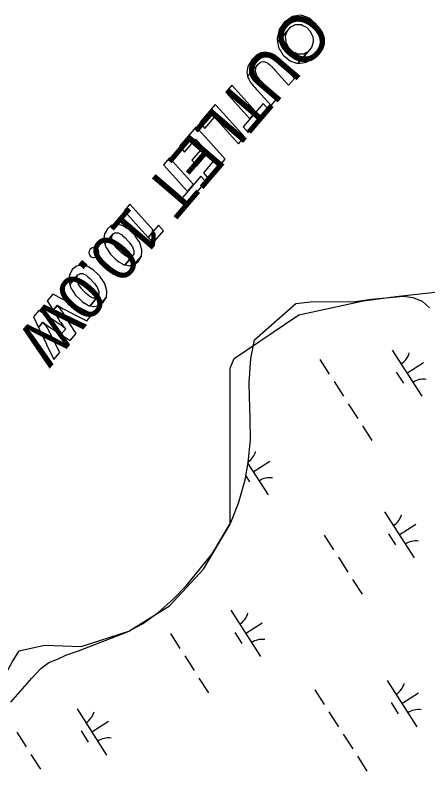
# Model space of a CAD drawing. Extents: x 3962991 to 3983549, y 181631 to 204078.
# Drawn here: x 3968944 to 3969320, y 196242 to 196933 of the extents above; entities that cross this region are included whole.
import ezdxf

# ---------------------------------------------------------------- set-up
doc = ezdxf.new("R2010")
doc.units = 0
for name, color, linetype in [('V-ANNO-MASK', 7, 'Continuous'), ('V-ANNO-MASK2', 7, 'Continuous'), ('V-RIVR-EDGE', 7, 'Continuous'), ('V-RIVR-IDEN', 7, 'Continuous'), ('V-WETL-SWMP', 7, 'Continuous')]:
    doc.layers.add(name, color=color, linetype=linetype)

msp = doc.modelspace()

# ---------------------------------------------------------------- linework, layer by layer
at = {"layer": 'V-ANNO-MASK2'}
for points in [[(3969192.19, 196929.26), (3969189.62, 196927.54), (3969184.44, 196920.23), (3969183.74, 196917.21), (3969182.53, 196912.13), (3969183.05, 196908.71), (3969191.78, 196918.91), (3969195.15, 196922.77), (3969199.45, 196924.93), (3969199.57, 196924.94), (3969201.66, 196924.97), (3969201.66, 196924.97), (3969204.3, 196925), (3969204.65, 196924.84), (3969206.08, 196924.12), (3969208.81, 196922.75), (3969209.02, 196922.54), (3969209.02, 196922.55), (3969209.52, 196922.04), (3969212.6, 196918.9), (3969212.6, 196918.9), (3969212.65, 196918.84), (3969212.78, 196918.58), (3969214.45, 196915.14), (3969215.02, 196913.96), (3969215.03, 196913.93), (3969215.36, 196910.44), (3969215.51, 196908.84), (3969215.52, 196908.77), (3969213.9, 196903.99), (3969213.89, 196903.95), (3969210.58, 196900.05), (3969201.51, 196889.45), (3969205.97, 196890.12), (3969209.18, 196890.6), (3969213.84, 196893.74), (3969215.94, 196895.15), (3969215.94, 196895.15), (3969220.98, 196902.08), (3969221.88, 196905.43), (3969223.13, 196910.17), (3969222.59, 196914.07), (3969222.59, 196914.11), (3969222.58, 196914.12), (3969222.23, 196916.61), (3969222.22, 196916.68), (3969222.01, 196918.2), (3969220.71, 196920.56), (3969220.7, 196920.59), (3969220.08, 196921.71), (3969218.27, 196924.99), (3969218.13, 196925.24), (3969218.09, 196925.31), (3969214.79, 196928.19), (3969214.26, 196928.66), (3969214.03, 196928.85), (3969211.8, 196930.8), (3969210.21, 196931.33), (3969209.83, 196931.45), (3969207.79, 196932.12), (3969206.18, 196932.65), (3969206.09, 196932.68), (3969204.18, 196933.31), (3969204.1, 196933.3), (3969200.19, 196932.74), (3969196.6, 196932.22)], [(3969191.74, 196918.78), (3969191.78, 196918.91), (3969183.05, 196908.71), (3969183.06, 196908.65), (3969183.06, 196908.65), (3969183.43, 196906.22), (3969183.44, 196906.1), (3969183.44, 196906.1), (3969183.75, 196904.05), (3969184.82, 196902.25), (3969185.02, 196901.92), (3969185.02, 196901.92), (3969185.86, 196900.51), (3969187.46, 196897.82), (3969187.62, 196897.55), (3969188, 196896.91), (3969191.37, 196894.12), (3969191.43, 196894.07), (3969191.64, 196893.9), (3969194.35, 196891.66), (3969195.59, 196891.27), (3969195.62, 196891.26), (3969198.23, 196890.45), (3969199.44, 196890.07), (3969199.49, 196890.06), (3969201.45, 196889.44), (3969201.47, 196889.45), (3969201.51, 196889.45), (3969210.58, 196900.05), (3969210.53, 196900.03), (3969210.5, 196900.01), (3969206.16, 196897.84), (3969206.04, 196897.78), (3969204.54, 196897.81), (3969201.28, 196897.88), (3969201.26, 196897.89), (3969200.15, 196898.44), (3969196.89, 196900.03), (3969196.71, 196900.22), (3969196.65, 196900.28), (3969193.58, 196903.42), (3969193.07, 196903.92), (3969192.93, 196904.21), (3969191.51, 196907.11), (3969190.76, 196908.62), (3969190.71, 196909.13), (3969190.41, 196911.84), (3969190.18, 196913.97), (3969190.26, 196914.19)], [(3969163.38, 196896.55), (3969159.37, 196892.39), (3969158.26, 196890.57), (3969156.15, 196887.11), (3969155.72, 196884.96), (3969155.04, 196881.58), (3969155.39, 196879.67), (3969155.74, 196877.75), (3969164.95, 196888.5), (3969167.47, 196890.58), (3969167.51, 196890.59), (3969168.21, 196890.75), (3969170.36, 196891.22), (3969170.48, 196891.19), (3969170.52, 196891.17), (3969173.15, 196890.4), (3969173.8, 196889.91), (3969173.98, 196889.77), (3969174.46, 196889.41), (3969175.65, 196888.51), (3969176.91, 196887.27), (3969177.39, 196886.79), (3969177.96, 196886.22), (3969178.05, 196886.13), (3969179.78, 196884.19), (3969180.83, 196883.02), (3969192.94, 196869.51), (3969198.3, 196875.77), (3969186.18, 196889.26), (3969185.12, 196890.43), (3969183.36, 196892.33), (3969183.27, 196892.42), (3969182.72, 196893.01), (3969182.24, 196893.49), (3969180.99, 196894.74), (3969179.93, 196895.79), (3969179.44, 196896.14), (3969179.25, 196896.27), (3969178.58, 196896.75), (3969176.54, 196898.19), (3969176.5, 196898.21), (3969176.38, 196898.25), (3969175.02, 196898.69), (3969174.57, 196898.84), (3969174.54, 196898.84), (3969173.97, 196899.03), (3969172.41, 196899.54), (3969170.25, 196899.35), (3969167.86, 196899.14), (3969165.07, 196897.53)], [(3969163.26, 196885.67), (3969164.95, 196888.5), (3969155.74, 196877.75), (3969155.87, 196877.04), (3969155.88, 196877.01), (3969155.98, 196876.46), (3969156.67, 196875.23), (3969156.73, 196875.12), (3969156.75, 196875.09), (3969158.04, 196872.77), (3969158.47, 196872.01), (3969158.58, 196871.79), (3969158.98, 196871.34), (3969159.95, 196870.19), (3969159.96, 196870.19), (3969161.12, 196868.82), (3969161.56, 196868.31), (3969162.09, 196867.69), (3969162.17, 196867.59), (3969163.9, 196865.66), (3969164.96, 196864.48), (3969177.07, 196850.98), (3969182.39, 196857.19), (3969170.31, 196870.73), (3969169.25, 196871.91), (3969167.54, 196873.85), (3969167.45, 196873.95), (3969166.92, 196874.56), (3969166.46, 196875.07), (3969165.4, 196876.55), (3969164.51, 196877.79), (3969164.15, 196878.29), (3969164.01, 196878.48), (3969163.72, 196879.39), (3969162.82, 196882.18), (3969162.81, 196882.22), (3969162.83, 196882.43), (3969163.1, 196884.77), (3969163.18, 196885.54)], [(3969163.09, 196845.24), (3969141.23, 196869.58), (3969135.87, 196863.33), (3969157.74, 196838.99)], [(3969130.96, 196846.84), (3969126.24, 196852.09), (3969112.04, 196835.51), (3969116.76, 196830.26), (3969125.61, 196840.59), (3969147.39, 196816.33), (3969152.74, 196822.57)], [(3969174.36, 196847.81), (3969169.72, 196852.99), (3969151.58, 196831.8), (3969156.21, 196826.62)], [(3969113.46, 196826.48), (3969108.77, 196831.69), (3969093.57, 196813.94), (3969098.26, 196808.73), (3969108.16, 196820.29), (3969114.77, 196812.93), (3969104.87, 196801.37), (3969109.45, 196796.28), (3969119.35, 196807.84), (3969125.3, 196801.2), (3969115.4, 196789.64), (3969120.08, 196784.43), (3969135.27, 196802.18), (3969130.6, 196807.38), (3969124.64, 196814.02), (3969120.07, 196819.12)], [(3969106.34, 196778.98), (3969084.48, 196803.32), (3969079.12, 196797.06), (3969100.99, 196772.72)], [(3969117.61, 196781.55), (3969112.97, 196786.72), (3969094.83, 196765.53), (3969099.46, 196760.36)], [(3969070.11, 196736.85), (3969048.33, 196761.11), (3969043.3, 196755.24), (3969065.08, 196730.97)], [(3969031.48, 196741.77), (3969027.9, 196738.85), (3969025.8, 196735.14), (3969025.2, 196734.09), (3969024.85, 196729.96), (3969024.71, 196728.31), (3969025.6, 196725.35), (3969033.06, 196734.06), (3969034.29, 196734.8), (3969035.08, 196735.27), (3969035.7, 196735.25), (3969035.7, 196735.25), (3969036.99, 196735.21), (3969037.39, 196735.19), (3969037.72, 196735.03), (3969040.39, 196733.68), (3969040.67, 196733.45), (3969042.1, 196732.26), (3969042.11, 196732.26), (3969043.77, 196730.87), (3969043.94, 196730.7), (3969044.52, 196730.09), (3969044.52, 196730.09), (3969047.31, 196727.17), (3969047.64, 196726.73), (3969048.09, 196726.1), (3969049.29, 196724.46), (3969050.51, 196722.78), (3969050.73, 196722.28), (3969051.84, 196719.67), (3969052.09, 196719.09), (3969052.14, 196717.25), (3969052.16, 196716.44), (3969052.17, 196716.04), (3969050.95, 196714.01), (3969044.02, 196705.91), (3969047.12, 196705.27), (3969047.82, 196705.12), (3969052.35, 196706.22), (3969058.93, 196713.91), (3969059.34, 196718.58), (3969059.44, 196719.65), (3969058.48, 196722.79), (3969058.34, 196723.24), (3969058.25, 196723.54), (3969058.06, 196724.16), (3969057.63, 196725.56), (3969057.43, 196726.19), (3969055.96, 196728.39), (3969055.68, 196728.82), (3969054.51, 196730.55), (3969053.37, 196732.27), (3969052.93, 196732.91), (3969052.55, 196733.28), (3969049.65, 196736.08), (3969049.04, 196736.66), (3969048.87, 196736.83), (3969047.3, 196738.33), (3969045.69, 196739.3), (3969045.37, 196739.5), (3969042.84, 196741.01), (3969042.53, 196741.2), (3969042.25, 196741.36), (3969041.38, 196741.88), (3969040.84, 196741.99), (3969040.51, 196742.06), (3969039.99, 196742.16), (3969037.08, 196742.76), (3969036, 196742.97), (3969031.87, 196741.87)], [(3969078.97, 196737.02), (3969074.52, 196741.99), (3969065.08, 196730.97), (3969069.53, 196726)], [(3969031.92, 196732.03), (3969033.06, 196734.06), (3969025.6, 196725.36), (3969025.76, 196724.83), (3969025.86, 196724.5), (3969026.02, 196723.95), (3969026.36, 196722.8), (3969026.37, 196722.81), (3969026.47, 196722.44), (3969026.59, 196722.04), (3969028.26, 196719.52), (3969028.47, 196719.2), (3969029.54, 196717.59), (3969030.78, 196715.71), (3969030.92, 196715.5), (3969031.52, 196714.92), (3969034.4, 196712.09), (3969034.78, 196711.72), (3969035.32, 196711.19), (3969036.74, 196709.8), (3969038.48, 196708.74), (3969038.91, 196708.48), (3969041.12, 196707.14), (3969041.6, 196706.85), (3969042.67, 196706.19), (3969043.28, 196706.07), (3969043.58, 196706.01), (3969044.02, 196705.91), (3969050.95, 196714.01), (3969049.89, 196713.37), (3969049.16, 196712.93), (3969048.44, 196712.94), (3969046.82, 196712.94), (3969046.3, 196713.19), (3969043.93, 196714.33), (3969043.54, 196714.65), (3969041.98, 196715.91), (3969040.44, 196717.17), (3969039.91, 196717.7), (3969039.53, 196718.09), (3969036.7, 196720.96), (3969036.19, 196721.65), (3969036.04, 196721.86), (3969034.72, 196723.64), (3969033.59, 196725.18), (3969033.43, 196725.56), (3969032.2, 196728.58), (3969032.05, 196728.95), (3969031.91, 196729.28), (3969031.92, 196730.84), (3969031.92, 196731.58)], [(3969013.61, 196721.22), (3969012.2, 196720.1), (3969011.31, 196718.53), (3969011.12, 196716.74), (3969011.59, 196715.03), (3969012.7, 196713.62), (3969014.27, 196712.73), (3969016.04, 196712.53), (3969017.75, 196713.02), (3969019.17, 196714.13), (3969020.05, 196715.71), (3969020.28, 196717.48), (3969019.8, 196719.19), (3969018.69, 196720.61), (3969017.12, 196721.48), (3969015.36, 196721.69)], [(3969058.69, 196713.49), (3969058.92, 196713.9), (3969052.35, 196706.22), (3969052.49, 196706.26), (3969056.34, 196709.42)], [(3968999.56, 196704.5), (3968995.99, 196701.58), (3968993.88, 196697.87), (3968993.29, 196696.82), (3968992.94, 196692.7), (3968992.8, 196691.04), (3968993.68, 196688.09), (3969001.14, 196696.8), (3969002.38, 196697.53), (3969003.16, 196698), (3969003.78, 196697.98), (3969003.79, 196697.99), (3969005.07, 196697.94), (3969005.48, 196697.93), (3969005.81, 196697.76), (3969008.47, 196696.42), (3969008.76, 196696.18), (3969010.19, 196694.99), (3969010.19, 196695), (3969011.85, 196693.61), (3969012.02, 196693.44), (3969012.6, 196692.82), (3969012.61, 196692.83), (3969015.4, 196689.9), (3969015.72, 196689.46), (3969016.18, 196688.84), (3969017.38, 196687.19), (3969018.6, 196685.52), (3969018.82, 196685.01), (3969019.93, 196682.4), (3969020.17, 196681.82), (3969020.23, 196679.99), (3969020.25, 196679.17), (3969020.26, 196678.77), (3969019.04, 196676.74), (3969012.11, 196668.65), (3969015.21, 196668), (3969015.9, 196667.85), (3969020.43, 196668.96), (3969027.01, 196676.64), (3969027.43, 196681.31), (3969027.52, 196682.38), (3969026.56, 196685.53), (3969026.42, 196685.97), (3969026.33, 196686.28), (3969026.14, 196686.9), (3969025.72, 196688.3), (3969025.52, 196688.93), (3969024.05, 196691.12), (3969023.76, 196691.55), (3969022.6, 196693.28), (3969021.46, 196695), (3969021.02, 196695.64), (3969020.63, 196696.02), (3969017.74, 196698.82), (3969017.13, 196699.4), (3969016.95, 196699.57), (3969015.39, 196701.07), (3969013.78, 196702.04), (3969013.45, 196702.23), (3969010.93, 196703.74), (3969010.62, 196703.93), (3969010.34, 196704.09), (3969009.47, 196704.62), (3969008.92, 196704.73), (3969008.6, 196704.8), (3969008.08, 196704.9), (3969005.17, 196705.49), (3969004.08, 196705.71), (3968999.96, 196704.61)], [(3969000.01, 196694.77), (3969001.14, 196696.8), (3968993.69, 196688.09), (3968993.84, 196687.57), (3968993.94, 196687.24), (3968994.11, 196686.69), (3968994.45, 196685.54), (3968994.45, 196685.54), (3968994.56, 196685.18), (3968994.68, 196684.77), (3968996.35, 196682.25), (3968996.56, 196681.94), (3968997.62, 196680.32), (3968998.87, 196678.45), (3968999, 196678.24), (3968999.61, 196677.65), (3969002.49, 196674.83), (3969002.87, 196674.45), (3969003.4, 196673.92), (3969004.83, 196672.53), (3969006.57, 196671.47), (3969007, 196671.21), (3969009.2, 196669.87), (3969009.69, 196669.58), (3969010.75, 196668.93), (3969011.37, 196668.8), (3969011.67, 196668.74), (3969012.11, 196668.65), (3969019.04, 196676.74), (3969017.97, 196676.1), (3969017.25, 196675.67), (3969016.53, 196675.67), (3969014.91, 196675.68), (3969014.39, 196675.93), (3969012.01, 196677.07), (3969011.63, 196677.38), (3969010.07, 196678.65), (3969008.52, 196679.9), (3969008, 196680.44), (3969007.62, 196680.82), (3969004.78, 196683.69), (3969004.27, 196684.39), (3969004.13, 196684.59), (3969002.81, 196686.38), (3969001.68, 196687.91), (3969001.52, 196688.3), (3969000.29, 196691.32), (3969000.13, 196691.69), (3969000, 196692.01), (3969000.01, 196693.57), (3969000.01, 196694.32)], [(3968987.12, 196674.63), (3968978.13, 196679.14), (3968973.03, 196673.18), (3968978.46, 196664.52), (3968982.42, 196669.15), (3968985.18, 196667.35), (3968985.63, 196667.11), (3968986.06, 196666.88), (3968986.21, 196666.79), (3968986.22, 196666.79), (3968987.69, 196665.98), (3968989, 196665.3), (3968989.69, 196664.93), (3968989.7, 196664.93), (3968992.47, 196663.48), (3968993.2, 196663.1), (3968993.2, 196663.11), (3968996.29, 196661.49), (3968996.43, 196661.41), (3968996.43, 196661.42), (3969009.07, 196654.82), (3969014.34, 196660.97), (3969001.54, 196667.39), (3969001.4, 196667.46), (3968998.28, 196669.03), (3968997.54, 196669.4), (3968994.74, 196670.81), (3968994.73, 196670.81), (3968994.02, 196671.17), (3968992.7, 196671.83), (3968991.19, 196672.59), (3968991.02, 196672.67), (3968990.58, 196672.89), (3968990.12, 196673.13)], [(3969026.77, 196676.22), (3969027.01, 196676.64), (3969020.43, 196668.96), (3969020.58, 196668.99), (3969024.42, 196672.15)], [(3968984.53, 196666.6), (3968982.42, 196669.15), (3968978.46, 196664.52), (3968980.27, 196661.62), (3968980.27, 196661.63), (3968980.55, 196661.18), (3968980.81, 196660.75), (3968980.91, 196660.59), (3968980.92, 196660.6), (3968981.83, 196659.14), (3968982.63, 196657.86), (3968983.05, 196657.18), (3968983.06, 196657.17), (3968984.75, 196654.47), (3968985.22, 196653.79), (3968987.21, 196650.89), (3968987.31, 196650.77), (3968989.98, 196647.66), (3968985.58, 196642.52), (3968993.92, 196637.13), (3968999.35, 196643.46), (3968993.86, 196652.2), (3968991.61, 196655.79), (3968991.53, 196655.93), (3968989.64, 196658.94), (3968989.19, 196659.65), (3968987.5, 196662.35), (3968987.49, 196662.36), (3968987.05, 196663.02), (3968986.22, 196664.26), (3968985.27, 196665.68), (3968985.16, 196665.83), (3968984.85, 196666.21)], [(3968973.69, 196658.95), (3968965.51, 196664.41), (3968960.5, 196658.56), (3968965.12, 196648.94), (3968969.25, 196653.77), (3968971.74, 196651.67), (3968972.12, 196651.34), (3968972.52, 196651.07), (3968972.52, 196651.07), (3968972.67, 196650.97), (3968974.03, 196650.03), (3968975.22, 196649.21), (3968975.87, 196648.79), (3968975.88, 196648.79), (3968978.46, 196647.12), (3968979.14, 196646.68), (3968982.02, 196644.82), (3968982.14, 196644.73), (3968982.15, 196644.74), (3968985.58, 196642.52), (3968989.98, 196647.66), (3968986.8, 196650.17), (3968986.67, 196650.26), (3968983.84, 196652.18), (3968983.17, 196652.63), (3968980.63, 196654.33), (3968980.62, 196654.34), (3968979.97, 196654.76), (3968978.77, 196655.57), (3968977.39, 196656.49), (3968977.24, 196656.58), (3968976.84, 196656.85), (3968976.42, 196657.13)], [(3968971.3, 196651.15), (3968969.25, 196653.77), (3968965.12, 196648.94), (3968966.65, 196645.73), (3968966.89, 196645.24), (3968967.12, 196644.76), (3968967.2, 196644.59), (3968967.98, 196642.97), (3968968.66, 196641.55), (3968969.02, 196640.79), (3968969.02, 196640.78), (3968969.03, 196640.79), (3968970.46, 196637.78), (3968970.46, 196637.79), (3968970.84, 196637), (3968972.45, 196633.64), (3968972.52, 196633.49), (3968972.52, 196633.5), (3968979.08, 196619.79), (3968984.52, 196626.14), (3968977.76, 196639.61), (3968977.68, 196639.76), (3968976.02, 196643.05), (3968975.63, 196643.82), (3968974.15, 196646.77), (3968974.15, 196646.78), (3968973.73, 196647.47), (3968972.93, 196648.75), (3968972.03, 196650.22), (3968971.91, 196650.36), (3968971.61, 196650.75)]]:
    msp.add_lwpolyline(points, close=True, dxfattribs=at)
at = {"layer": 'V-RIVR-EDGE'}
msp.add_lwpolyline([(3968838.75, 196205.76), (3968882.29, 196262.1), (3968916.87, 196300.52), (3968941.2, 196344.06), (3968947.6, 196354.31), (3968970.65, 196359.43), (3969003.95, 196358.15), (3969047.49, 196372.24), (3969084.63, 196395.29), (3969115.37, 196428.59), (3969139.7, 196469.57), (3969139.7, 196522.07), (3969139.7, 196574.58), (3969139.7, 196611.72), (3969143.54, 196620.68), (3969202.45, 196660.38), (3969261.36, 196673.19), (3969290.81, 196677.03), (3969348.44, 196683.43)], dxfattribs=at)
at = {"layer": 'V-WETL-SWMP'}
for p, q in [((3969199.68, 196670.62), (3969213.08, 196672.12)), ((3969213.08, 196672.12), (3969253.57, 196672.59)), ((3969253.57, 196672.59), (3969268.66, 196674.58)), ((3969268.66, 196674.58), (3969297.64, 196677.34)), ((3969297.64, 196677.34), (3969306.11, 196676.23)), ((3969306.11, 196676.23), (3969314.62, 196672.7)), ((3969314.62, 196672.7), (3969321.33, 196666.73)), ((3969162.11, 196637.68), (3969199.68, 196670.62)), ((3969158.68, 196620.72), (3969162.11, 196637.68)), ((3969287.34, 196628.33), (3969314.33, 196586.24)), ((3969157.13, 196598.34), (3969158.68, 196620.72)), ((3969221.46, 196619.85), (3969230.1, 196606.38)), ((3969300.84, 196607.28), (3969315.99, 196617)), ((3969291.1, 196608.17), (3969297.58, 196598.07)), ((3969157.28, 196585.64), (3969157.13, 196598.34)), ((3969234.42, 196599.65), (3969243.05, 196586.18)), ((3969158.11, 196566.31), (3969157.28, 196585.64)), ((3969247.37, 196579.45), (3969256, 196565.98)), ((3969158.34, 196546.37), (3969158.11, 196566.31)), ((3969260.32, 196559.24), (3969268.96, 196545.77)), ((3969156.16, 196525.8), (3969158.34, 196546.37)), ((3969160.8, 196517.51), (3969175.96, 196527.22)), ((3969153.32, 196510.05), (3969156.16, 196525.8)), ((3969156.01, 196524.98), (3969174.3, 196496.46)), ((3969154, 196513.82), (3969157.55, 196508.29)), ((3969147.53, 196488.83), (3969153.32, 196510.05)), ((3969140.48, 196471.22), (3969147.53, 196488.83)), ((3969280.34, 196481.01), (3969307.32, 196438.92)), ((3969123.29, 196442.61), (3969140.48, 196471.22)), ((3969293.83, 196459.97), (3969308.98, 196469.68)), ((3969225.43, 196459.72), (3969234.07, 196446.25)), ((3969284.1, 196460.85), (3969290.57, 196450.75)), ((3969113.16, 196429.8), (3969123.29, 196442.61)), ((3969238.38, 196439.51), (3969247.02, 196426.04)), ((3969100.05, 196413.93), (3969113.16, 196429.8)), ((3969251.34, 196419.31), (3969259.97, 196405.84)), ((3969088.1, 196401.71), (3969100.05, 196413.93)), ((3969073.75, 196388.85), (3969088.1, 196401.71)), ((3969059.96, 196379.02), (3969073.75, 196388.85)), ((3969140.3, 196391.24), (3969167.29, 196349.15)), ((3969046.14, 196371.6), (3969059.96, 196379.02)), ((3969153.8, 196370.19), (3969168.95, 196379.91)), ((3969001.62, 196354.16), (3969046.14, 196371.6)), ((3969085.4, 196369.94), (3969094.03, 196356.47)), ((3969144.06, 196371.08), (3969150.54, 196360.98)), ((3968990.18, 196350.4), (3969001.62, 196354.16)), ((3968982.37, 196346.68), (3968990.18, 196350.4)), ((3969098.35, 196349.74), (3969106.99, 196336.27)), ((3968967.36, 196338.05), (3968974.55, 196343.57)), ((3968974.55, 196343.57), (3968982.37, 196346.68)), ((3968959, 196329.49), (3968967.36, 196338.05)), ((3968939.91, 196307.51), (3968959, 196329.49)), ((3969111.31, 196329.53), (3969119.94, 196316.06)), ((3969282.75, 196327.29), (3969309.74, 196285.2)), ((3969216.87, 196318.81), (3969225.51, 196305.34)), ((3969296.25, 196306.24), (3969311.4, 196315.96)), ((3969286.51, 196307.13), (3969292.99, 196297.03)), ((3969000.27, 196301.47), (3969027.26, 196259.37)), ((3969229.83, 196298.61), (3969238.46, 196285.14)), ((3969013.77, 196280.42), (3969028.92, 196290.13)), ((3968945.37, 196280.17), (3968954, 196266.7)), ((3969004.03, 196281.31), (3969010.51, 196271.2)), ((3969242.78, 196278.41), (3969251.41, 196264.94)), ((3968958.32, 196259.96), (3968966.96, 196246.5)), ((3969255.73, 196258.2), (3969264.37, 196244.73))]:
    msp.add_line(p, q, dxfattribs=at)
for centre, start, end in [((3969286.13, 196630.66), 301.89187, 343.43553), ((3969315.94, 196584.16), 81.89186, 123.43552), ((3969146.1, 196540.89), 305.11318, 343.43553), ((3969175.91, 196494.38), 81.89186, 123.43552), ((3969279.12, 196483.35), 301.89187, 343.43553), ((3969308.94, 196436.84), 81.89186, 123.43552), ((3969139.09, 196393.57), 301.89187, 343.43553), ((3969168.9, 196347.07), 81.89186, 123.43552), ((3969281.54, 196329.62), 301.89187, 343.43553), ((3968999.06, 196303.8), 301.89187, 343.43553), ((3969311.35, 196283.12), 81.89186, 123.43552), ((3969028.87, 196257.29), 81.89186, 123.43552)]:
    msp.add_arc(centre, 17.62, start, end, dxfattribs=at)

# ---------------------------------------------------------------- texts
at = {"layer": 'V-ANNO-MASK'}
msp.add_text('OUTLET 10.0W', height=41.9999, rotation=229.42316, dxfattribs=at).set_placement((3969203.15, 196941.89))
at = {"layer": 'V-RIVR-IDEN'}
msp.add_text('OUTLET 10.0W', height=41.9999, rotation=229.42316, dxfattribs=at).set_placement((3969203.15, 196941.89))

doc.saveas('drawing.dxf')
